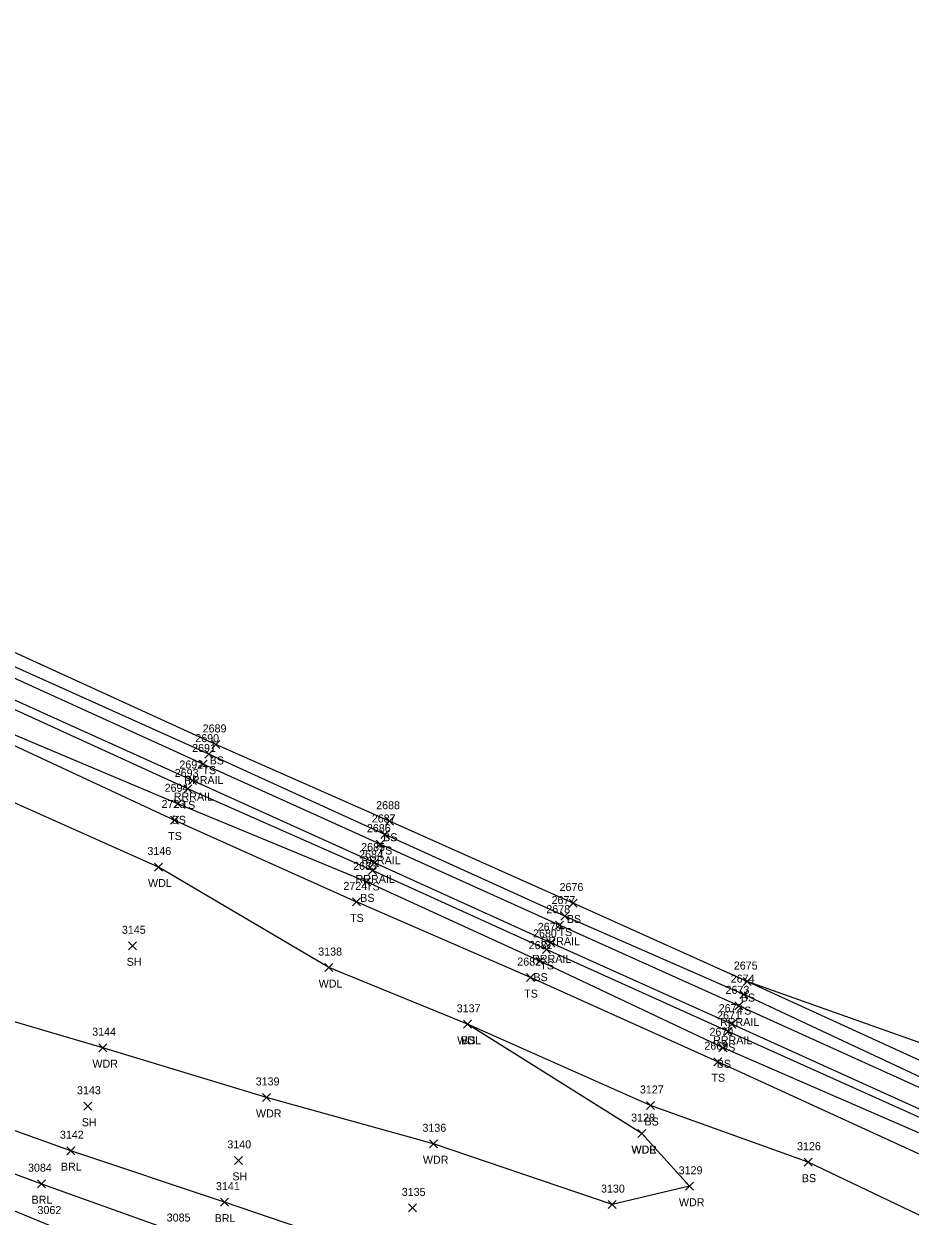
# Model space of a CAD drawing. Extents: x 1599569 to 1610055, y 642560 to 647860.
# Drawn here: x 1600583 to 1600804.5, y 647459.9 to 647757.9 of the extents above; entities that cross this region are included whole.
import ezdxf

# ---------------------------------------------------------------- set-up
doc = ezdxf.new("R2010")
doc.units = 0
for name, color, linetype in [('L_A', 7, 'Continuous'), ('L_I', 7, 'Continuous'), ('L_TIC', 7, 'Continuous'), ('LABL', 7, 'Continuous'), ('LAWA', 7, 'Continuous'), ('LELB', 7, 'Continuous'), ('LSOGP', 7, 'Continuous'), ('R_A', 7, 'Continuous'), ('R_I', 7, 'Continuous'), ('R_TIC', 7, 'Continuous'), ('RR', 7, 'Continuous')]:
    doc.layers.add(name, color=color, linetype=linetype)

msp = doc.modelspace()

# ---------------------------------------------------------------- linework, layer by layer
at = {"layer": 'L_TIC'}
for points in [[(1600629.97, 647576.79), (1600631.97, 647578.79)], [(1600631.97, 647576.79), (1600629.97, 647578.79)], [(1600628.19, 647574.36), (1600630.19, 647576.36)], [(1600630.19, 647574.36), (1600628.19, 647576.36)], [(1600622.99, 647565.68), (1600624.99, 647567.68)], [(1600624.99, 647565.68), (1600622.99, 647567.68)], [(1600620.46, 647561.95), (1600622.46, 647563.95)], [(1600622.46, 647561.95), (1600620.46, 647563.95)], [(1600619.64, 647557.9), (1600621.64, 647559.9)], [(1600621.64, 647557.9), (1600619.64, 647559.9)], [(1600673.33, 647557.6), (1600675.33, 647559.6)], [(1600675.33, 647557.6), (1600673.33, 647559.6)], [(1600672.22, 647554.28), (1600674.22, 647556.28)], [(1600674.22, 647554.28), (1600672.22, 647556.28)], [(1600615.59, 647546.15), (1600617.59, 647548.15)], [(1600617.59, 647546.15), (1600615.59, 647548.15)], [(1600669.07, 647545.31), (1600671.07, 647547.31)], [(1600671.07, 647545.31), (1600669.07, 647547.31)], [(1600667.58, 647542.44), (1600669.58, 647544.44)], [(1600669.58, 647542.44), (1600667.58, 647544.44)], [(1600665.09, 647537.44), (1600667.09, 647539.44)], [(1600667.09, 647537.44), (1600665.09, 647539.44)], [(1600665.09, 647537.44), (1600667.09, 647539.44)], [(1600667.09, 647537.44), (1600665.09, 647539.44)], [(1600719.23, 647537.15), (1600721.23, 647539.15)], [(1600721.23, 647537.15), (1600719.23, 647539.15)], [(1600717.17, 647533.9), (1600719.17, 647535.9)], [(1600719.17, 647533.9), (1600717.17, 647535.9)], [(1600609.16, 647526.46), (1600611.16, 647528.46)], [(1600611.16, 647526.46), (1600609.16, 647528.46)], [(1600712.63, 647525.56), (1600714.63, 647527.56)], [(1600714.63, 647525.56), (1600712.63, 647527.56)], [(1600658.23, 647521.02), (1600660.23, 647523.02)], [(1600660.23, 647521.02), (1600658.23, 647523.02)], [(1600710.89, 647522.62), (1600712.89, 647524.62)], [(1600712.89, 647522.62), (1600710.89, 647524.62)], [(1600708.6, 647518.51), (1600710.6, 647520.51)], [(1600710.6, 647518.51), (1600708.6, 647520.51)], [(1600762.72, 647517.52), (1600764.72, 647519.52)], [(1600764.72, 647517.52), (1600762.72, 647519.52)], [(1600761.95, 647514.26), (1600763.95, 647516.26)], [(1600763.95, 647514.26), (1600761.95, 647516.26)], [(1600692.85, 647506.84), (1600694.85, 647508.84)], [(1600694.85, 647506.84), (1600692.85, 647508.84)], [(1600692.85, 647506.84), (1600694.85, 647508.84)], [(1600694.85, 647506.84), (1600692.85, 647508.84)], [(1600757.97, 647505.06), (1600759.97, 647507.06)], [(1600759.97, 647505.06), (1600757.97, 647507.06)], [(1600601.74, 647500.99), (1600603.74, 647502.99)], [(1600603.74, 647500.99), (1600601.74, 647502.99)], [(1600756.71, 647500.96), (1600758.71, 647502.96)], [(1600758.71, 647500.96), (1600756.71, 647502.96)], [(1600755.41, 647497.48), (1600757.41, 647499.48)], [(1600757.41, 647497.48), (1600755.41, 647499.48)], [(1600642.61, 647488.56), (1600644.61, 647490.56)], [(1600644.61, 647488.56), (1600642.61, 647490.56)], [(1600597.94, 647486.36), (1600599.94, 647488.36)], [(1600599.94, 647486.36), (1600597.94, 647488.36)], [(1600738.63, 647486.55), (1600740.63, 647488.55)], [(1600740.63, 647486.55), (1600738.63, 647488.55)], [(1600736.44, 647479.52), (1600738.44, 647481.52)], [(1600738.44, 647479.52), (1600736.44, 647481.52)], [(1600736.44, 647479.52), (1600738.44, 647481.52)], [(1600738.44, 647479.52), (1600736.44, 647481.52)], [(1600593.68, 647475.25), (1600595.68, 647477.25)], [(1600595.68, 647475.25), (1600593.68, 647477.25)], [(1600684.34, 647476.97), (1600686.34, 647478.97)], [(1600686.34, 647476.97), (1600684.34, 647478.97)], [(1600635.6, 647472.83), (1600637.6, 647474.83)], [(1600637.6, 647472.83), (1600635.6, 647474.83)], [(1600777.97, 647472.37), (1600779.97, 647474.37)], [(1600779.97, 647472.37), (1600777.97, 647474.37)], [(1600586.34, 647467), (1600588.34, 647469)], [(1600588.34, 647467), (1600586.34, 647469)], [(1600748.33, 647466.35), (1600750.33, 647468.35)], [(1600750.33, 647466.35), (1600748.33, 647468.35)], [(1600632.1, 647462.38), (1600634.1, 647464.38)], [(1600634.1, 647462.38), (1600632.1, 647464.38)], [(1600679.11, 647460.94), (1600681.11, 647462.94)], [(1600681.11, 647460.94), (1600679.11, 647462.94)], [(1600729, 647461.77), (1600731, 647463.77)], [(1600731, 647461.77), (1600729, 647463.77)]]:
    msp.add_lwpolyline(points, dxfattribs=at)
at = {"layer": 'LABL'}
msp.add_lwpolyline([(1600549.16, 647482.12), (1600587.34, 647468), (1600622.01, 647455.54), (1600659.72, 647441.77), (1600697.35, 647428.92), (1600725.07, 647418.09), (1600758.35, 647406.43), (1600789.53, 647394.65), (1600829.98, 647379.88), (1600858.93, 647365.17), (1600893.05, 647356.35), (1600928.59, 647369.58), (1600886.67, 647382.78), (1600843.57, 647394.9), (1600799.84, 647407.24), (1600758.94, 647419.51), (1600717.33, 647433.23), (1600675.44, 647448.96), (1600633.1, 647463.38), (1600594.68, 647476.25), (1600537.7, 647496.6)], dxfattribs=at)
at = {"layer": 'LAWA'}
for points in [[(1600737.44, 647480.52), (1600749.33, 647467.35), (1600730, 647462.77), (1600685.34, 647477.97), (1600643.61, 647489.56), (1600602.74, 647501.99), (1600542.89, 647519.56), (1600513.51, 647532.8), (1600459.11, 647556.92), (1600407.56, 647581.09), (1600365.84, 647597.55), (1600328.36, 647614.3), (1600286.9, 647630.81), (1600248.27, 647645.58), (1600208.97, 647660.75), (1600170.58, 647674.95), (1600134.14, 647689.04), (1600090.43, 647707.15), (1600050.9, 647710.69), (1600009.49, 647721.85), (1599974.8, 647749.03), (1599978.26, 647757.91)], [(1600737.44, 647480.52), (1600693.85, 647507.84), (1600659.23, 647522.02), (1600616.59, 647547.15), (1600572.91, 647566.58), (1600531.29, 647582.2), (1600493.06, 647599.22), (1600436.17, 647627), (1600386.77, 647647.65)]]:
    msp.add_lwpolyline(points, dxfattribs=at)
at = {"layer": 'LELB'}
for points in [[(1600821.34, 647492.23), (1600763.72, 647518.52), (1600720.23, 647538.15), (1600674.33, 647558.6), (1600630.97, 647577.79), (1600579.4, 647601.35), (1600532.57, 647622.07), (1600481.31, 647645.17), (1600444.94, 647660.58)], [(1600819.14, 647488.99), (1600762.95, 647515.26), (1600718.17, 647534.9), (1600673.22, 647555.28), (1600629.19, 647575.36), (1600577.72, 647598.52), (1600531.3, 647619.46), (1600479.73, 647642.44), (1600444.01, 647658.36)], [(1600814.78, 647480.92), (1600758.97, 647506.06), (1600713.63, 647526.56), (1600670.07, 647546.31), (1600623.99, 647566.68), (1600574.12, 647589.4), (1600526.65, 647611.13), (1600476.12, 647633.7), (1600438.96, 647650.21)], [(1600813.3, 647477.78), (1600757.71, 647501.96), (1600711.89, 647523.62), (1600668.58, 647543.44), (1600621.46, 647562.95), (1600572.35, 647583.62), (1600525.05, 647608.35), (1600474.28, 647631.11), (1600437.92, 647647.06)], [(1600435.87, 647643.54), (1600485.28, 647620.13), (1600533.23, 647598.06), (1600574.03, 647580.51), (1600620.64, 647558.9), (1600666.09, 647538.44)], [(1601065.14, 647298.7), (1601017.93, 647308.63), (1600970.12, 647319.08), (1600922.99, 647332.86), (1600876.04, 647347.67), (1600828.44, 647364.9), (1600781.51, 647382.96), (1600734.1, 647401.33), (1600686.53, 647420.21), (1600637.49, 647439.52), (1600589.75, 647457.41), (1600542.23, 647476.94), (1600495.72, 647495.2), (1600449.86, 647513.12), (1600405.19, 647531.59), (1600383.83, 647541.02), (1600357.09, 647550.14)], [(1601042.57, 647341.43), (1601046.92, 647357.23), (1601002.18, 647385.23), (1600956.28, 647405.31), (1600905.33, 647430.67), (1600858.96, 647452.27), (1600808.26, 647474.67), (1600756.41, 647498.48), (1600709.6, 647519.51), (1600666.09, 647538.44)], [(1601006.37, 647351.71), (1601004.39, 647364.75), (1600971.27, 647379.2), (1600939.3, 647396.5), (1600905.82, 647416.24), (1600860.62, 647437.22), (1600817.41, 647455.03), (1600778.97, 647473.37), (1600739.63, 647487.55), (1600693.85, 647507.84)]]:
    msp.add_lwpolyline(points, dxfattribs=at)
at = {"layer": 'LSOGP'}
msp.add_lwpolyline([(1600824.54, 647496.94), (1600763.73, 647518.52), (1600720.23, 647538.15), (1600674.33, 647558.6), (1600630.97, 647577.79), (1600579.41, 647601.35), (1600532.57, 647622.07), (1600481.31, 647645.17), (1600444.94, 647660.58), (1600444.02, 647658.36), (1600438.96, 647650.21), (1600437.92, 647647.06), (1600435.87, 647643.54), (1600386.78, 647647.65), (1600336.85, 647631.6), (1600286.9, 647630.81), (1600248.28, 647645.58), (1600208.97, 647660.74), (1600170.58, 647674.94), (1600134.14, 647689.04), (1600090.44, 647707.15), (1600057.63, 647725.77)], dxfattribs=at)
at = {"layer": 'R_TIC'}
for points in [[(1600626.76, 647571.9), (1600628.76, 647573.9)], [(1600628.76, 647571.9), (1600626.76, 647573.9)], [(1600624.14, 647567.77), (1600626.14, 647569.77)], [(1600626.14, 647567.77), (1600624.14, 647569.77)], [(1600671.06, 647551.85), (1600673.06, 647553.85)], [(1600673.06, 647551.85), (1600671.06, 647553.85)], [(1600669.58, 647547.16), (1600671.58, 647549.16)], [(1600671.58, 647547.16), (1600669.58, 647549.16)], [(1600715.86, 647531.61), (1600717.86, 647533.61)], [(1600717.86, 647531.61), (1600715.86, 647533.61)], [(1600713.71, 647527.2), (1600715.71, 647529.2)], [(1600715.71, 647527.2), (1600713.71, 647529.2)], [(1600760.67, 647511.45), (1600762.67, 647513.45)], [(1600762.67, 647511.45), (1600760.67, 647513.45)], [(1600758.94, 647506.87), (1600760.94, 647508.87)], [(1600760.94, 647506.87), (1600758.94, 647508.87)]]:
    msp.add_lwpolyline(points, dxfattribs=at)
at = {"layer": 'RR'}
for points in [[(1600817.98, 647486.96), (1600761.67, 647512.45), (1600716.86, 647532.61), (1600672.06, 647552.85), (1600627.76, 647572.9), (1600576.59, 647596.11), (1600529.83, 647617.1), (1600478.79, 647640.16), (1600442.67, 647656.44)], [(1600815.63, 647482.59), (1600759.94, 647507.87), (1600714.71, 647528.2), (1600670.58, 647548.16), (1600625.14, 647568.77), (1600574.89, 647591.45), (1600527.65, 647612.71), (1600476.73, 647635.64), (1600440.18, 647652.11)]]:
    msp.add_lwpolyline(points, dxfattribs=at)

# ---------------------------------------------------------------- texts
at = {"layer": 'L_A'}
for s, p in [('TS', (1600627.6, 647570.36)), ('BS', (1600629.41, 647572.79)), ('TS', (1600622.4, 647561.68)), ('BS', (1600619.9, 647557.95)), ('TS', (1600619.04, 647553.9)), ('BS', (1600672.77, 647553.6)), ('TS', (1600671.63, 647550.28)), ('WDL', (1600614, 647542.15)), ('TS', (1600668.48, 647541.31)), ('BS', (1600667.03, 647538.44)), ('TS', (1600664.5, 647533.44)), ('TS', (1600664.5, 647533.44)), ('BS', (1600718.67, 647533.15)), ('TS', (1600716.58, 647529.9)), ('SH', (1600608.65, 647522.46)), ('TS', (1600712.04, 647521.56)), ('WDL', (1600656.65, 647517.02)), ('BS', (1600710.33, 647518.62)), ('TS', (1600708.01, 647514.51)), ('BS', (1600762.17, 647513.52)), ('TS', (1600761.36, 647510.26)), ('WDL', (1600691.26, 647502.84)), ('BS', (1600692.29, 647502.84)), ('TS', (1600757.38, 647501.06)), ('WDR', (1600600.1, 647496.99)), ('BS', (1600756.15, 647496.96)), ('TS', (1600754.82, 647493.48)), ('WDR', (1600640.97, 647484.56)), ('SH', (1600597.43, 647482.36)), ('BS', (1600738.08, 647482.55)), ('WDR', (1600734.8, 647475.52)), ('WDL', (1600734.86, 647475.52)), ('WDR', (1600682.7, 647472.97)), ('BRL', (1600592.22, 647471.25)), ('SH', (1600635.09, 647468.83)), ('BS', (1600777.41, 647468.37)), ('BRL', (1600584.88, 647463)), ('WDR', (1600746.69, 647462.35)), ('BRL', (1600630.65, 647458.38))]:
    msp.add_text(s, height=2, dxfattribs=at).set_placement(p)
at = {"layer": 'L_I'}
for s, p in [('2689', (1600627.65, 647580.79)), ('2690', (1600625.8, 647578.36)), ('2693', (1600620.68, 647569.68)), ('2694', (1600618.15, 647565.95)), ('2723', (1600617.38, 647561.9)), ('2688', (1600671.02, 647561.6)), ('2687', (1600669.92, 647558.28)), ('3146', (1600613.84, 647550.15)), ('2684', (1600666.76, 647549.31)), ('2683', (1600665.28, 647546.44)), ('2724', (1600662.83, 647541.44)), ('2724', (1600662.83, 647541.44)), ('2676', (1600716.86, 647541.15)), ('2677', (1600714.86, 647537.9)), ('3145', (1600607.47, 647530.46)), ('2680', (1600710.23, 647529.56)), ('2681', (1600709.14, 647526.62)), ('3138', (1600656.54, 647525.02)), ('2682', (1600706.29, 647522.51)), ('2675', (1600760.42, 647521.52)), ('2674', (1600759.64, 647518.26)), ('3137', (1600691.15, 647510.84)), ('3137', (1600691.15, 647510.84)), ('2671', (1600756.23, 647509.06)), ('3144', (1600600.05, 647504.99)), ('2670', (1600754.32, 647504.96)), ('2669', (1600753.05, 647501.48)), ('3143', (1600596.25, 647490.36)), ('3139', (1600640.91, 647492.56)), ('3127', (1600736.94, 647490.55)), ('3136', (1600682.59, 647480.97)), ('3128', (1600734.75, 647483.52)), ('3128', (1600734.75, 647483.52)), ('3142', (1600591.98, 647479.25)), ('3140', (1600633.82, 647476.83)), ('3126', (1600776.22, 647476.37)), ('3084', (1600584, 647471)), ('3129', (1600746.63, 647470.35)), ('3141', (1600630.98, 647466.38)), ('3135', (1600677.42, 647464.94)), ('3130', (1600727.22, 647465.77)), ('3062', (1600586.37, 647460.41)), ('3085', (1600618.67, 647458.54))]:
    msp.add_text(s, height=2, dxfattribs=at).set_placement(p)
at = {"layer": 'R_A'}
for p in [(1600623.05, 647567.9), (1600620.43, 647563.77), (1600667.35, 647547.85), (1600665.87, 647543.16), (1600712.15, 647527.61), (1600710, 647523.2), (1600756.96, 647507.45), (1600755.23, 647502.87)]:
    msp.add_text('RRRAIL', height=2, dxfattribs=at).set_placement(p)
at = {"layer": 'R_I'}
for s, p in [('2691', (1600625.02, 647575.9)), ('2692', (1600621.83, 647571.77)), ('2686', (1600668.7, 647555.85)), ('2685', (1600667.27, 647551.16)), ('2678', (1600713.55, 647535.61)), ('2679', (1600711.4, 647531.2)), ('2673', (1600758.36, 647515.45)), ('2672', (1600756.63, 647510.87))]:
    msp.add_text(s, height=2, dxfattribs=at).set_placement(p)

doc.saveas('drawing.dxf')
